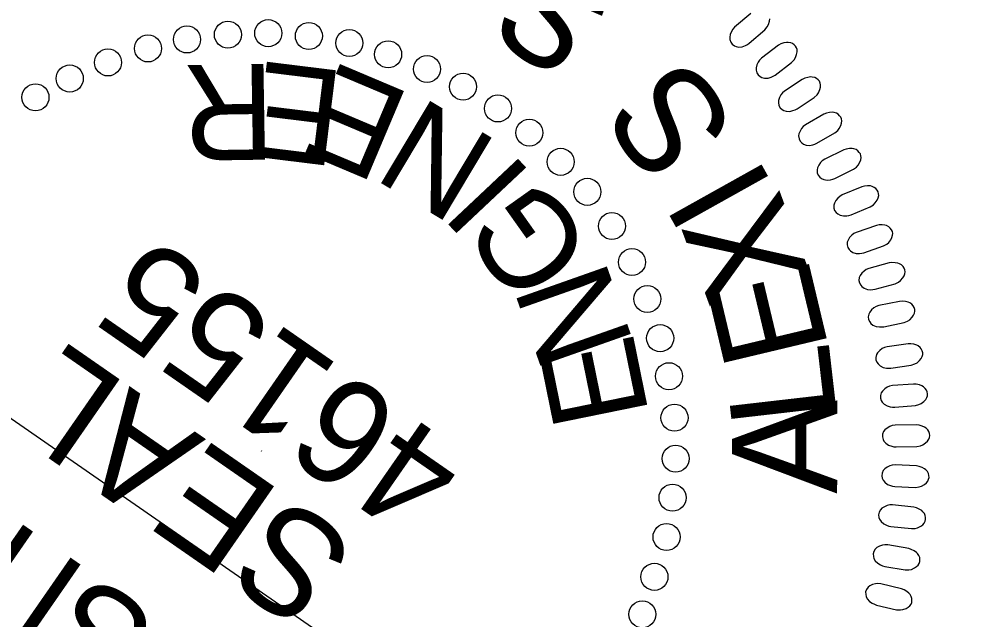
# Model space of a CAD drawing. Extents: x 478372 to 480379, y 492840 to 494699.
# Drawn here: x 478483.3 to 478539.3, y 493852.2 to 493887.7 of the extents above; entities that cross this region are included whole.
import ezdxf

# ---------------------------------------------------------------- set-up
doc = ezdxf.new("R2010")
doc.units = 0
for name, color, linetype in [('Sheet PE Seal Cell', 7, 'Continuous'), ('Sheet Sticker Exception Certification CELL', 7, 'Continuous'), ('Sheet Sticker Incomplete CELL', 7, 'Continuous')]:
    doc.layers.add(name, color=color, linetype=linetype)

msp = doc.modelspace()

# ---------------------------------------------------------------- linework, layer by layer
at = {"layer": 'Sheet PE Seal Cell'}
msp.add_line((478497.686, 493862.115), (478497.713, 493862.154), dxfattribs=at)
msp.add_lwpolyline([(478526.651, 493888.036), (478525.695, 493887.221), (478525.582, 493887.092), (478525.505, 493886.967), (478525.443, 493886.795), (478525.411, 493886.619), (478525.414, 493886.493), (478525.471, 493886.335), (478525.554, 493886.209), (478525.682, 493886.122), (478525.788, 493886.076), (478525.947, 493886.044), (478526.153, 493886.065), (478526.333, 493886.131), (478526.45, 493886.194), (478526.558, 493886.267), (478527.486, 493887.069), (478527.627, 493887.24), (478527.7, 493887.371), (478527.755, 493887.568), (478527.774, 493887.713)], dxfattribs=at)
for points in [[(478528.091, 493884.384), (478529.068, 493885.127), (478529.22, 493885.289), (478529.3, 493885.415), (478529.367, 493885.607), (478529.396, 493885.751), (478529.391, 493885.889), (478529.36, 493885.996), (478529.308, 493886.097), (478529.224, 493886.174), (478529.127, 493886.252), (478529.017, 493886.299), (478528.874, 493886.321), (478528.774, 493886.321), (478528.614, 493886.284), (478528.435, 493886.223), (478528.295, 493886.145), (478527.29, 493885.39), (478527.168, 493885.269), (478527.085, 493885.149), (478527.012, 493884.981), (478526.968, 493884.808), (478526.964, 493884.682), (478527.011, 493884.521), (478527.085, 493884.39), (478527.208, 493884.295), (478527.311, 493884.242), (478527.467, 493884.201), (478527.674, 493884.208), (478527.858, 493884.264), (478527.979, 493884.318)], [(478529.392, 493882.384), (478530.413, 493883.064), (478530.576, 493883.216), (478530.663, 493883.337), (478530.742, 493883.525), (478530.78, 493883.666), (478530.783, 493883.804), (478530.759, 493883.913), (478530.713, 493884.018), (478530.635, 493884.099), (478530.543, 493884.183), (478530.436, 493884.237), (478530.295, 493884.268), (478530.195, 493884.274), (478530.034, 493884.247), (478529.851, 493884.198), (478529.705, 493884.128), (478528.655, 493883.438), (478528.526, 493883.326), (478528.436, 493883.211), (478528.352, 493883.048), (478528.298, 493882.878), (478528.285, 493882.752), (478528.322, 493882.588), (478528.389, 493882.452), (478528.505, 493882.351), (478528.604, 493882.291), (478528.757, 493882.24), (478528.965, 493882.235), (478529.152, 493882.279), (478529.276, 493882.325)], [(478530.566, 493880.343), (478531.627, 493880.957), (478531.798, 493881.1), (478531.893, 493881.214), (478531.984, 493881.397), (478532.031, 493881.536), (478532.043, 493881.672), (478532.026, 493881.783), (478531.986, 493881.89), (478531.913, 493881.977), (478531.828, 493882.066), (478531.724, 493882.126), (478531.584, 493882.167), (478531.485, 493882.179), (478531.322, 493882.163), (478531.137, 493882.125), (478530.987, 493882.064), (478529.896, 493881.442), (478529.76, 493881.337), (478529.662, 493881.228), (478529.568, 493881.071), (478529.504, 493880.904), (478529.484, 493880.78), (478529.511, 493880.614), (478529.568, 493880.474), (478529.677, 493880.365), (478529.773, 493880.299), (478529.923, 493880.239), (478530.129, 493880.221), (478530.319, 493880.253), (478530.445, 493880.292)], [(478531.627, 493878.26), (478532.725, 493878.806), (478532.905, 493878.938), (478533.007, 493879.046), (478533.109, 493879.222), (478533.164, 493879.358), (478533.186, 493879.494), (478533.175, 493879.606), (478533.142, 493879.715), (478533.075, 493879.806), (478532.995, 493879.9), (478532.895, 493879.968), (478532.759, 493880.016), (478532.661, 493880.035), (478532.497, 493880.028), (478532.309, 493880.002), (478532.156, 493879.951), (478531.028, 493879.398), (478530.887, 493879.303), (478530.781, 493879.2), (478530.678, 493879.049), (478530.603, 493878.887), (478530.575, 493878.764), (478530.591, 493878.597), (478530.64, 493878.454), (478530.742, 493878.338), (478530.833, 493878.266), (478530.979, 493878.197), (478531.184, 493878.166), (478531.375, 493878.185), (478531.504, 493878.216)], [(478532.592, 493876.111), (478533.723, 493876.588), (478533.911, 493876.707), (478534.019, 493876.809), (478534.132, 493876.979), (478534.195, 493877.11), (478534.225, 493877.245), (478534.222, 493877.357), (478534.196, 493877.468), (478534.135, 493877.563), (478534.061, 493877.663), (478533.965, 493877.735), (478533.832, 493877.793), (478533.735, 493877.817), (478533.571, 493877.822), (478533.383, 493877.807), (478533.227, 493877.766), (478532.066, 493877.285), (478531.919, 493877.198), (478531.807, 493877.103), (478531.695, 493876.958), (478531.61, 493876.801), (478531.574, 493876.68), (478531.579, 493876.512), (478531.619, 493876.367), (478531.715, 493876.244), (478531.801, 493876.167), (478531.941, 493876.088), (478532.144, 493876.044), (478532.336, 493876.052), (478532.467, 493876.075)], [(478533.349, 493873.866), (478534.508, 493874.271), (478534.702, 493874.378), (478534.817, 493874.474), (478534.941, 493874.635), (478535.012, 493874.764), (478535.05, 493874.896), (478535.054, 493875.007), (478535.035, 493875.12), (478534.98, 493875.219), (478534.911, 493875.322), (478534.821, 493875.402), (478534.692, 493875.467), (478534.598, 493875.498), (478534.434, 493875.511), (478534.245, 493875.509), (478534.087, 493875.478), (478532.898, 493875.071), (478532.745, 493874.994), (478532.628, 493874.905), (478532.507, 493874.768), (478532.411, 493874.617), (478532.369, 493874.498), (478532.363, 493874.33), (478532.394, 493874.182), (478532.481, 493874.054), (478532.563, 493873.972), (478532.698, 493873.885), (478532.898, 493873.828), (478533.09, 493873.824), (478533.222, 493873.838)], [(478534.014, 493871.7), (478535.196, 493872.031), (478535.397, 493872.127), (478535.518, 493872.214), (478535.651, 493872.368), (478535.73, 493872.491), (478535.777, 493872.621), (478535.787, 493872.732), (478535.776, 493872.846), (478535.727, 493872.947), (478535.665, 493873.055), (478535.58, 493873.139), (478535.455, 493873.213), (478535.362, 493873.25), (478535.2, 493873.274), (478535.011, 493873.284), (478534.851, 493873.262), (478533.639, 493872.93), (478533.482, 493872.863), (478533.36, 493872.782), (478533.23, 493872.653), (478533.126, 493872.508), (478533.075, 493872.392), (478533.06, 493872.225), (478533.081, 493872.075), (478533.16, 493871.943), (478533.237, 493871.855), (478533.367, 493871.76), (478533.562, 493871.69), (478533.754, 493871.673), (478533.886, 493871.68)], [(478534.531, 493869.48), (478535.731, 493869.736), (478535.937, 493869.818), (478536.063, 493869.898), (478536.205, 493870.043), (478536.293, 493870.162), (478536.347, 493870.288), (478536.364, 493870.398), (478536.36, 493870.512), (478536.318, 493870.617), (478536.263, 493870.728), (478536.183, 493870.818), (478536.064, 493870.899), (478535.974, 493870.941), (478535.813, 493870.977), (478535.625, 493870.997), (478535.464, 493870.986), (478534.233, 493870.731), (478534.073, 493870.674), (478533.945, 493870.6), (478533.808, 493870.48), (478533.695, 493870.341), (478533.637, 493870.23), (478533.611, 493870.064), (478533.623, 493869.912), (478533.693, 493869.775), (478533.764, 493869.683), (478533.887, 493869.579), (478534.078, 493869.498), (478534.268, 493869.47), (478534.401, 493869.467)], [(478534.943, 493867.03), (478536.157, 493867.21), (478536.368, 493867.278), (478536.499, 493867.351), (478536.65, 493867.486), (478536.744, 493867.599), (478536.807, 493867.722), (478536.831, 493867.831), (478536.834, 493867.945), (478536.798, 493868.053), (478536.75, 493868.167), (478536.676, 493868.261), (478536.562, 493868.35), (478536.475, 493868.397), (478536.316, 493868.443), (478536.13, 493868.475), (478535.969, 493868.474), (478534.725, 493868.297), (478534.56, 493868.25), (478534.429, 493868.185), (478534.284, 493868.073), (478534.163, 493867.942), (478534.098, 493867.834), (478534.062, 493867.67), (478534.064, 493867.519), (478534.125, 493867.377), (478534.191, 493867.281), (478534.307, 493867.169), (478534.493, 493867.076), (478534.681, 493867.036), (478534.813, 493867.026)], [(478535.175, 493864.714), (478536.397, 493864.818), (478536.612, 493864.873), (478536.747, 493864.937), (478536.907, 493865.063), (478537.008, 493865.169), (478537.078, 493865.287), (478537.109, 493865.395), (478537.119, 493865.509), (478537.09, 493865.618), (478537.05, 493865.735), (478536.982, 493865.834), (478536.873, 493865.93), (478536.789, 493865.983), (478536.634, 493866.038), (478536.45, 493866.082), (478536.29, 493866.091), (478535.036, 493865.993), (478534.87, 493865.956), (478534.734, 493865.899), (478534.583, 493865.797), (478534.453, 493865.673), (478534.382, 493865.57), (478534.335, 493865.408), (478534.328, 493865.257), (478534.381, 493865.112), (478534.439, 493865.012), (478534.549, 493864.893), (478534.728, 493864.789), (478534.913, 493864.736), (478535.044, 493864.718)], [(478535.255, 493862.368), (478536.482, 493862.395), (478536.7, 493862.437), (478536.84, 493862.491), (478537.006, 493862.608), (478537.114, 493862.707), (478537.191, 493862.821), (478537.229, 493862.926), (478537.247, 493863.04), (478537.224, 493863.151), (478537.192, 493863.27), (478537.13, 493863.373), (478537.027, 493863.475), (478536.946, 493863.534), (478536.795, 493863.598), (478536.615, 493863.654), (478536.455, 493863.673), (478535.199, 493863.653), (478535.029, 493863.627), (478534.891, 493863.579), (478534.733, 493863.486), (478534.596, 493863.371), (478534.518, 493863.272), (478534.461, 493863.114), (478534.445, 493862.964), (478534.488, 493862.815), (478534.54, 493862.712), (478534.642, 493862.586), (478534.814, 493862.471), (478534.996, 493862.407), (478535.126, 493862.38)], [(478535.178, 493860.018), (478536.405, 493859.968), (478536.625, 493859.995), (478536.767, 493860.042), (478536.941, 493860.147), (478537.055, 493860.239), (478537.139, 493860.348), (478537.183, 493860.451), (478537.208, 493860.563), (478537.192, 493860.675), (478537.167, 493860.796), (478537.112, 493860.903), (478537.016, 493861.012), (478536.94, 493861.075), (478536.793, 493861.148), (478536.616, 493861.215), (478536.458, 493861.244), (478535.202, 493861.304), (478535.032, 493861.289), (478534.89, 493861.249), (478534.727, 493861.166), (478534.583, 493861.06), (478534.499, 493860.966), (478534.433, 493860.812), (478534.407, 493860.663), (478534.441, 493860.512), (478534.486, 493860.406), (478534.581, 493860.274), (478534.745, 493860.148), (478534.922, 493860.073), (478535.05, 493860.038)], [(478534.946, 493857.654), (478536.167, 493857.527), (478536.388, 493857.541), (478536.533, 493857.579), (478536.713, 493857.672), (478536.833, 493857.758), (478536.923, 493857.861), (478536.974, 493857.961), (478537.005, 493858.071), (478536.997, 493858.184), (478536.979, 493858.306), (478536.931, 493858.416), (478536.843, 493858.531), (478536.77, 493858.599), (478536.628, 493858.681), (478536.456, 493858.759), (478536.299, 493858.798), (478535.05, 493858.936), (478534.879, 493858.931), (478534.736, 493858.901), (478534.568, 493858.828), (478534.418, 493858.732), (478534.328, 493858.643), (478534.252, 493858.493), (478534.217, 493858.346), (478534.241, 493858.194), (478534.279, 493858.084), (478534.365, 493857.948), (478534.522, 493857.811), (478534.693, 493857.725), (478534.819, 493857.682)], [(478534.582, 493855.292), (478535.792, 493855.088), (478536.014, 493855.088), (478536.161, 493855.116), (478536.347, 493855.199), (478536.471, 493855.277), (478536.569, 493855.374), (478536.625, 493855.471), (478536.664, 493855.578), (478536.662, 493855.692), (478536.652, 493855.815), (478536.611, 493855.928), (478536.53, 493856.047), (478536.462, 493856.12), (478536.325, 493856.211), (478536.158, 493856.3), (478536.004, 493856.348), (478534.766, 493856.565), (478534.595, 493856.571), (478534.45, 493856.55), (478534.279, 493856.488), (478534.121, 493856.401), (478534.027, 493856.318), (478533.942, 493856.173), (478533.897, 493856.028), (478533.912, 493855.875), (478533.944, 493855.763), (478534.021, 493855.621), (478534.168, 493855.476), (478534.334, 493855.379), (478534.457, 493855.328)], [(478534.09, 493853.005), (478535.285, 493852.725), (478535.508, 493852.712), (478535.655, 493852.73), (478535.846, 493852.801), (478535.975, 493852.871), (478536.078, 493852.962), (478536.14, 493853.054), (478536.186, 493853.159), (478536.192, 493853.272), (478536.19, 493853.396), (478536.156, 493853.511), (478536.082, 493853.636), (478536.018, 493853.713), (478535.887, 493853.812), (478535.727, 493853.911), (478535.576, 493853.97), (478534.355, 493854.263), (478534.184, 493854.28), (478534.038, 493854.268), (478533.863, 493854.217), (478533.701, 493854.14), (478533.601, 493854.063), (478533.507, 493853.924), (478533.453, 493853.783), (478533.458, 493853.629), (478533.483, 493853.515), (478533.551, 493853.369), (478533.689, 493853.214), (478533.849, 493853.107), (478533.968, 493853.049)]]:
    msp.add_lwpolyline(points, close=True, dxfattribs=at)
for centre in [(478495.7, 493886.778), (478498.088, 493886.866), (478500.493, 493886.7), (478490.968, 493885.961), (478493.276, 493886.492), (478502.889, 493886.282), (478505.185, 493885.61), (478488.6, 493885.132), (478507.488, 493884.739), (478486.339, 493884.179), (478509.622, 493883.694), (478484.308, 493883.068), (478511.685, 493882.407), (478513.547, 493880.969), (478515.402, 493879.245), (478516.981, 493877.47), (478518.434, 493875.443), (478519.619, 493873.311), (478520.528, 493871.128), (478521.29, 493868.805), (478521.81, 493866.552), (478522.139, 493864.094), (478522.203, 493861.673), (478522.022, 493859.36), (478521.668, 493857.035), (478520.949, 493854.673), (478520.233, 493852.454)]:
    msp.add_circle(centre, 0.801, dxfattribs=at)
at = {"layer": 'Sheet Sticker Incomplete CELL'}
msp.add_lwpolyline([(478594.874, 493786.337), (478581.479, 493767.028), (478460.695, 493850.814), (478474.089, 493870.123)], close=True, dxfattribs=at)

# ---------------------------------------------------------------- texts
at = {"layer": 'Sheet PE Seal Cell'}
for s, height, rotation, p in [('S', 6.236, 144.6342, (478519.016, 493888.891)), ('E', 5.669, 172.9754, (478502.707, 493884.593)), ('R', 5.669, 180.9152, (478498.425, 493885.054)), ('E', 5.669, 157.0958, (478506.692, 493883.196)), ('S', 6.236, 126.039, (478526.008, 493881.213)), ('N', 5.669, 149.156, (478511.843, 493880.361)), ('I', 5.669, 133.2764, (478513.836, 493878.403)), ('I', 6.236, 119.1934, (478528.047, 493877.738)), ('G', 5.669, 125.3366, (478517.497, 493873.807)), ('X', 6.236, 110.246, (478530.204, 493872.517)), ('46155', 6.2363, 145.233, (478510.091, 493861.768)), ('N', 5.669, 109.457, (478519.753, 493868.472)), ('E', 6.236, 103.4004, (478531.305, 493868.135)), ('E', 5.669, 101.5172, (478520.644, 493864.256)), ('SEAL', 6.2363, 145.233, (478503.557, 493856.469)), ('L', 6.236, 96.5547, (478531.778, 493864.057)), ('A', 6.236, 89.9351, (478531.767, 493859.585))]:
    msp.add_text(s, height=height, rotation=rotation, dxfattribs=at).set_placement(p)
at = {"layer": 'Sheet Sticker Exception Certification CELL'}
for s, p in [('UNLESS ALL SIGNATURES COMPLETED', (478646.498, 493842.27)), ('UNLESS ALL SIGNATURES COMPLETED', (478646.498, 493842.27)), ('DOCUMENT NOT CONSIDERED FINAL', (478637.316, 493837.93)), ('DOCUMENT NOT CONSIDERED FINAL', (478637.316, 493837.93))]:
    msp.add_text(s, height=5.5, rotation=145.2516, dxfattribs=at).set_placement(p)
at = {"layer": 'Sheet Sticker Incomplete CELL'}
for s, height, p in [('INCOMPLETE PLANS', 11.52, (478580.851, 493781.825)), ('DO NOT USE FOR R/W ACQUISITION', 5.76, (478582.142, 493789.388))]:
    msp.add_text(s, height=height, rotation=145.2516, dxfattribs=at).set_placement(p)

doc.saveas('drawing.dxf')
